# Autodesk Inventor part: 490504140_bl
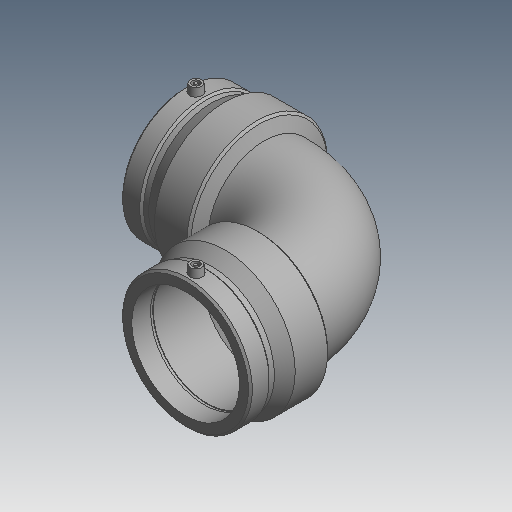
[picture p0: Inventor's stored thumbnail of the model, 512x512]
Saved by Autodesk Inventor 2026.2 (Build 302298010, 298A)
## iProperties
Created: 2017-06
Part Number: 490504140_bl
Material: Generic
Description: PLASSON 90° ELBOW 140
Document SubType Name: Modeling
Designer: KIM
Mass: 55.0731 g
Surface Area: 148.067 cm^2
Volume: 55.0731 cm^3
Density: 1 g/cm^3
Appearance: Default
Author: KIM
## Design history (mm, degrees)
derived "490504.ipt"
feature "Solid1::490504.ipt" dims "ScaleForDerivedMember" = 10
tag "TaggingFeature1"
body "Solid1"
other parameters: "d2" = 183 [user parameter], "d4" = 77.25 [user parameter], "d5" = 164.7 [user parameter], "d8" = 168 deg [user parameter], "d10" = 37.2 [user parameter], "d11" = 12.4 [user parameter], "d14" = 17.6296 [user parameter], "d19" = 3.52592 [user parameter], "d20" = 168 deg [user parameter], "d22" = 168.36 [user parameter], "d23" = 183 [user parameter], "d24" = 163.3092 [user parameter], "d29" = 94 [user parameter], "d30" = 15 [user parameter], "d31" = 108.15 [user parameter], "d34" = 5 deg [user parameter], "d35" = 15 [user parameter], "d39" = 5 deg [user parameter], "d41" = 4 [user parameter], "d42" = 14 [user parameter], "d43" = 0 [user parameter], "d45" = 4 [user parameter], "d46" = 14 [user parameter], "d47" = 0 [user parameter], "d50" = 119 [user parameter], "d51" = 37.2 [user parameter], "d52" = 93 [user parameter], "d54" = 90 deg [user parameter], "d67" = 45 deg [user parameter], "d71" = 90 deg [user parameter], "d75" = 9.15 [user parameter], "d82" = 45 deg [user parameter], "d83" = 93 [user parameter], "d84" = 164.7 [user parameter], "d87" = 90 deg [user parameter], "d90" = 93 [user parameter], "d91" = 0 [user parameter], "d92" = 93 [user parameter], "d93" = 0 [user parameter], "d94" = 90 deg [user parameter], "d101" = 3 [user parameter], "d102" = 0 [user parameter], "d103" = 3 [user parameter], "d104" = 0 [user parameter], "d105" = 26.97 [user parameter], "d106" = 6.7425 [user parameter], "d110" = 51.15 [user parameter], "d111" = 309 [user parameter], "d112" = 309 [user parameter], "d113" = 309 [user parameter], "d114" = 309 [user parameter], "L_" = 309 [user parameter], "L_1" = 93 [user parameter], "D_" = 183 [user parameter], "A_" = 94 [user parameter], "d_2" = 12 [user parameter]
